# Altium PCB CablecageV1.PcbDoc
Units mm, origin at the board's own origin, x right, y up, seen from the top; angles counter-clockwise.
Board outline 55.12 x 24.93 mm, 2 copper layers (Top Layer, Bottom Layer); 4 components, 15 nets, 52 pads, 14 vias.
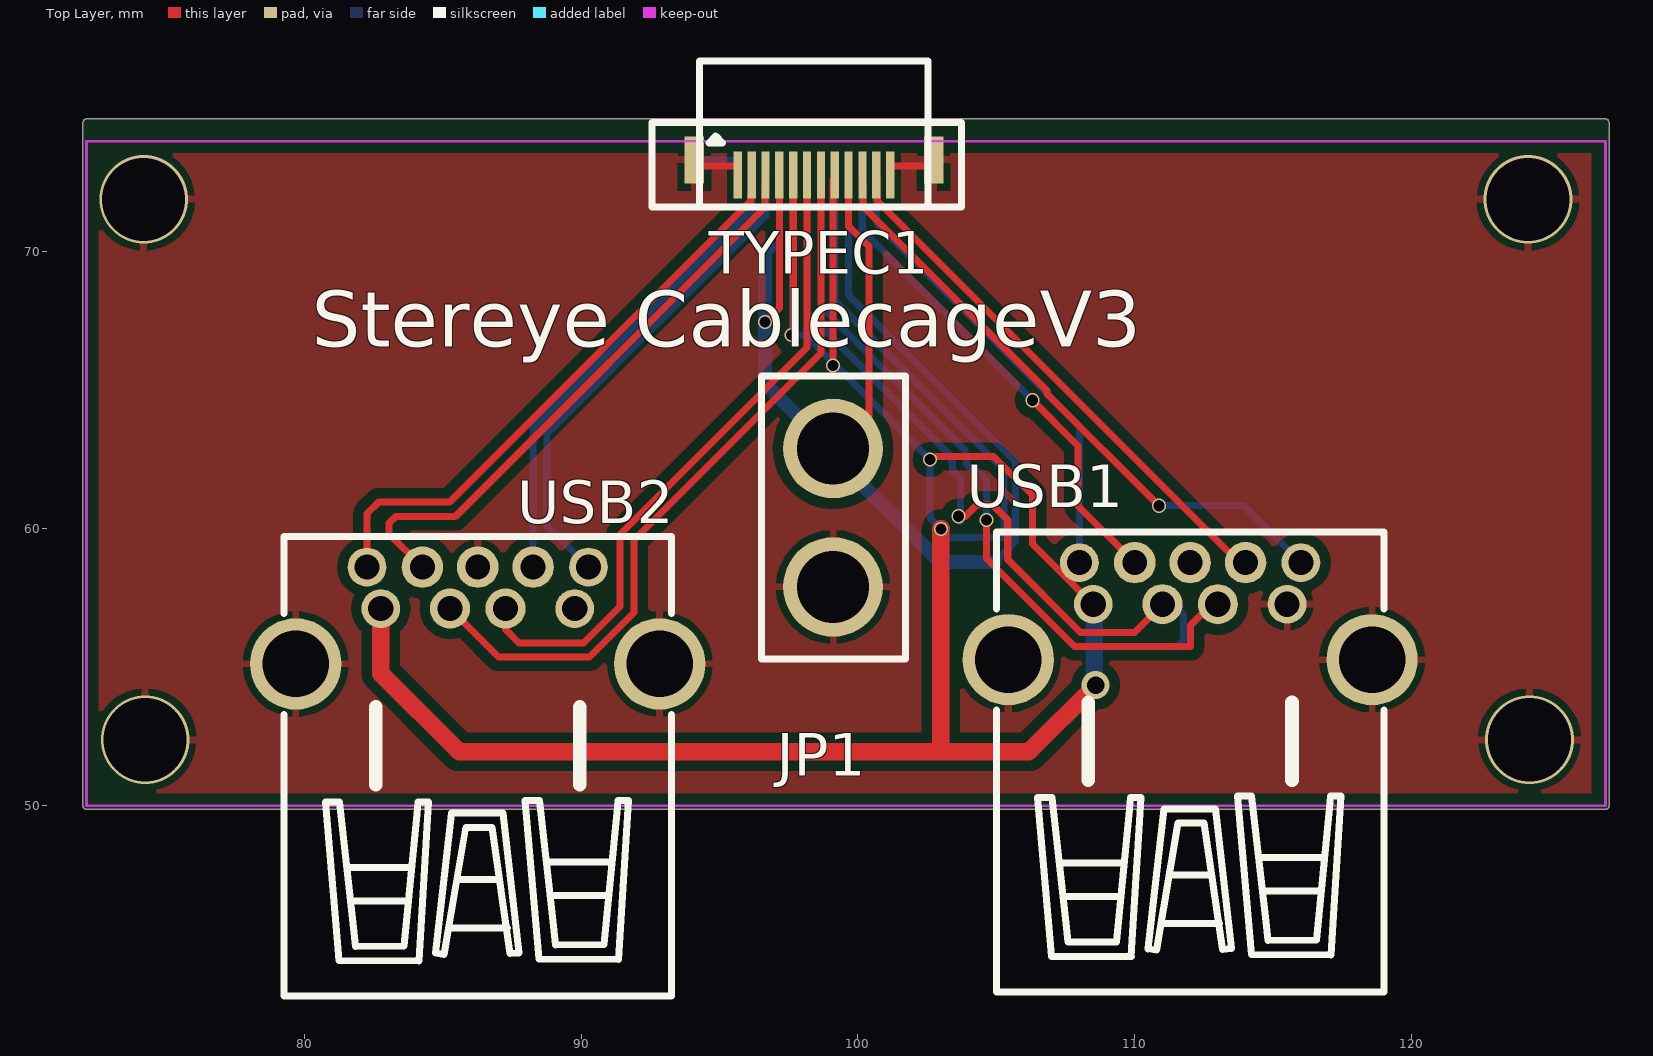
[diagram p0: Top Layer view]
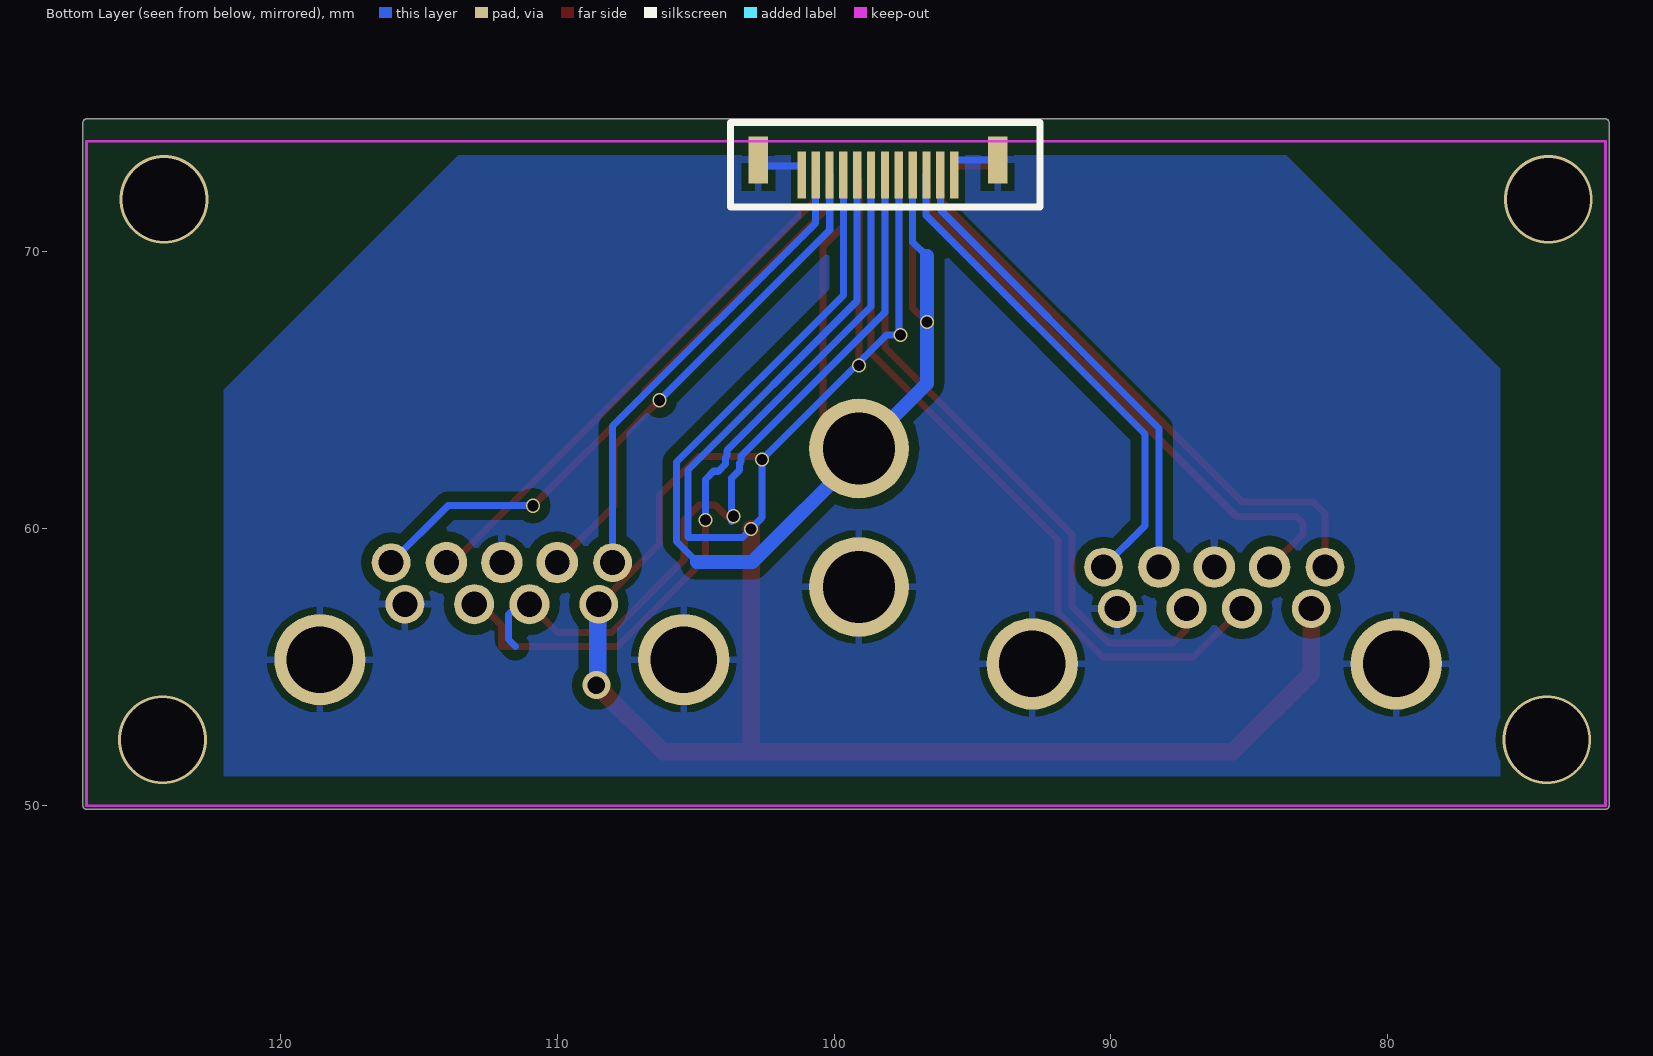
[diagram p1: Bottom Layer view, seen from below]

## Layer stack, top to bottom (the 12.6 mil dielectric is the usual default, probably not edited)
Top Solder: solder mask 0.0102, Solder Resist, Dk 3.5
Top Layer: signal copper 0.0356
Dielectric 1: dielectric 0.32, FR-4, Dk 4.8
Bottom Layer: signal copper 0.0356
Bottom Solder: solder mask 0.0102, Solder Resist, Dk 3.5

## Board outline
72.009,50 ccw(c72.136,50) 72.136,49.873 127,49.873 ccw(c127,50) 127.127,50 127.127,74.676 ccw(c127,74.676) 127,74.803 72.136,74.803 ccw(c72.136,74.676) 72.009,74.676

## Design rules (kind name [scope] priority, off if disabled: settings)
Clearance [All] p1: gap=0.152 ignorepadtopadclearanceinfootprint=TRUE except(0: Arc-Hole Track-Hole SMDPad-Hole THPad-Hole Via-Hole Fill-Hole Poly-Hole Region-Hole Text-Hole; 0.381: Arc-Fill Arc-Poly Arc-Region Track-Fill Track-Poly Track-Region SMDPad-Fill SMDPad-Poly SMDPad-Region THPad-Fill THPad-Poly THPad-Region Via-Fill Via-Poly Via-Region Fill-Fill Fill-Poly Fill-Region Poly-Poly Poly-Region Region-Region)
DiffPairsRouting [All] p1: maxlimit=0.381 minlimit=0.152 mostfreqgap=0.254 toplayer_minwidth=0.152 toplayer_maxwidth=0.381 toplayer_prefwidth=0.254 bottomlayer_minwidth=0.152 bottomlayer_maxwidth=0.381 bottomlayer_prefwidth=0.254 maxuncoupledlength=12.7
PlaneConnect [All] p1: planeconnectstyle=Relief reliefexpansion=0.508 reliefentries=4 reliefconductorwidth=0.381 reliefairgap=0.381
PolygonConnect [All] p1: connectstyle=Relief reliefconductorwidth=0.254 reliefentries=4 polygonreliefangle="90 Angle" airgapwidth=0.254
RoutingVias [All] p1: holewidth=0.711 width=1.27 viastyle="Through Hole" minholewidth=0.711 minwidth=1.27 maxholewidth=0.711 maxwidth=1.27
SolderMaskExpansion [All] p1: expansion=0.102
Width [All] p1: maxlimit=1.27 minlimit=0.152 preferedwidth=0.254 minimp=50.000000 maximp=50.000000 favimp=50.000000
28 further rules are at their usual default settings.

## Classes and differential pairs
differential pair USB3-T: +USB3-T_P -USB3-T_N
differential pair USB3-T2: +USB3-T2_P -USB3-T2_N
differential pair USB3-R: +USB3-R_P -USB3-R_N
differential pair USB3-R2: +USB3-R2_P -USB3-R2_N
differential pair D4: +D4_P -D4_N
differential pair D3: +D3_P -D3_N

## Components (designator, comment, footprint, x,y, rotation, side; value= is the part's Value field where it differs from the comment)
JP1 "HDR-1X2" XT30 99.1,60.4 r270 top
TYPEC1 "USB31-TYPEC-33141-2FS" TypeC-Chaban24P 98.41,71.628 r90 top
USB1 "FUS301-FDBU1K" USB3.0-A-TH_FUS301-FDBU1K 111.998,57.027 r0 top
USB2 "FUS301-FDBU1K" USB3.0-A-TH_FUS301-FDBU1K 86.267,56.868 r0 top

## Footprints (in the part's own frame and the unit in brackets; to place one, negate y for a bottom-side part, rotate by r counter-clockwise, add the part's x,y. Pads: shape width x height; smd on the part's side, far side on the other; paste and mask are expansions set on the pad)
TypeC-Chaban24P [mm]
  rect 1.7x0.7 smd: 0(1.693,4.317) 0(1.693,-4.323)
  rect 1.7x0.7 smd far side: 0(1.693,4.317) 0(1.693,-4.323)
  rect 1.7x0.3 smd: A1(1.143,2.747) A2(1.143,2.248) A3(1.143,1.748) A4(1.143,1.247) A5(1.143,0.747) A6(1.143,0.247) A7(1.143,-0.253) A8(1.143,-0.752) A9(1.143,-1.252) A10(1.143,-1.751) A11(1.143,-2.252) A12(1.143,-2.753)
  rect 1.7x0.3 smd far side: B1(1.143,-2.753) B2(1.143,-2.253) B3(1.143,-1.753) B4(1.143,-1.254) B5(1.143,-0.754) B6(1.143,-0.254) B7(1.143,0.247) B8(1.143,0.748) B9(1.143,1.248) B10(1.143,1.748) B11(1.143,2.247) B12(1.143,2.747)
  silkscreen extent -0.01,-5.33 5.27,5.84
USB3.0-A-TH_FUS301-FDBU1K [mm]
  round 1.4 hole 0.914: 1(-3.5,0.25) 4(3.5,0.25)
  round 1.45 hole 0.914: 2(-1,0.25) 3(1,0.25)
  round 1.4 hole 0.9: 5(4,1.75) 9(-4,1.75)
  round 1.5 hole 0.9: 6(2,1.75) 7(0,1.75) 8(-2,1.75)
  round 3.3 hole 2.4: 10(-6.57,-1.75) 10(6.57,-1.75)
  silkscreen extent -7,-13.75 7,2.85
XT30 [mm]
  round 3.6 hole 2.6: 1(-2.5,0) 2(2.5,0)
  silkscreen extent -5.12,-2.59 5.09,2.62

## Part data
JP1: library part "Header 2", "2P接插件"
TYPEC1: BOM_JLCPCB Part Class="Extended Part", BOM_Manufacturer="XKB Enterprise"
USB1 USB2: BOM_JLCPCB Part Class="Extended Part", BOM_Manufacturer=TXGA

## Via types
v1: diameter 0.508, hole 0.4, Top Layer to Bottom Layer, 9 vias
v2: diameter 3.2, hole 3, Top Layer to Bottom Layer, 4 vias
v3: diameter 1.016, hole 0.635, Top Layer to Bottom Layer, 1 vias

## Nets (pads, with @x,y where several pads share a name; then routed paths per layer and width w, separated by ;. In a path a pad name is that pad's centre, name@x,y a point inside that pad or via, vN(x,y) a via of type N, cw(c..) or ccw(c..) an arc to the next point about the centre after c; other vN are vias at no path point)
5V: TYPEC1.A5 TYPEC1.A8 TYPEC1.B5 TYPEC1.B8 USB1.1 USB2.1 | length 96.2
  Top Layer w0.254: v1@97.663,67 TYPEC1.A5 ; v1(99.1,65.9) 99.1,72.609 TYPEC1.A8@99.162,72.671 ; v1@102.8,62.6 102.811,62.611 104.902,62.611 106.299,61.214 106.299,59.455 108.477,57.277 USB1.1
  Top Layer w0.635: USB2.1 82.767,54.774 85.598,51.943 102.997,51.943 ; v1(103,60) 102.997,59.997 102.997,51.943 ; v3(108.585,54.356) 106.172,51.943 102.997,51.943
  Bottom Layer w0.254: TYPEC1.B8 97.661,67.061 v1(97.6,67) 98.1,67 v1(102.6,62.5) 102.6,60.4 v1(103,60) 103.313,59.687 105.258,59.687 105.283,59.712 105.283,60.444 105.279,60.448 105.279,62.121 99.163,68.237 TYPEC1.B5
  Bottom Layer w0.635: USB1.1 108.542,57.234 108.542,54.399 v3(108.585,54.356)
24V: JP1.1 TYPEC1.A4 TYPEC1.A9 TYPEC1.B4 TYPEC1.B9 | length 51.9
  Top Layer w0.254: v1(96.647,67.464) 97.162,67.98 TYPEC1.A4 ; TYPEC1.A9 99.661,70.939 100.4,70.2 100.4,63.57 JP1.1@100.203,63.373
  Bottom Layer w0.254: 96.647,69.843 97.162,70.358 TYPEC1.B9 ; TYPEC1.B4 99.663,68.437 105.686,62.414 105.686,60.616 105.689,60.613 105.689,59.543 104.946,58.8
  Bottom Layer w0.508: 96.647,69.843 v1(96.647,67.464) 96.647,65.253 JP1.1@98.9,63 ; JP1.1 99.1,62.653 102.953,58.8 104.946,58.8 ; JP1.1@99.419,62.45 JP1.1@100.243,63.274
D3_N: TYPEC1.A7 USB2.2 | length 26.6
  Top Layer w0.254: USB2.2 87.013,55.372 90.297,55.372 91.908,56.983 91.908,59.59 98.662,66.344 TYPEC1.A7
D3_P: TYPEC1.A6 USB2.3 | length 24
  Top Layer w0.254: USB2.3 87.267,56.37 87.757,55.88 90.087,55.88 91.4,57.193 91.4,59.8 98.154,66.554 TYPEC1.A6@98.154,72.771
D4_N: TYPEC1.B7 USB1.2 | length 27.7
  Top Layer w0.254: v1(103.632,60.452) 103.886,60.452 104.292,60.858 104.869,60.858 105.41,60.317 105.41,58.884 108.033,56.261 109.982,56.261 USB1.2
  Bottom Layer w0.254: TYPEC1.B7 98.162,67.819 103.353,62.629 103.353,62.422 103.406,62.368 103.406,62.126 103.695,61.837 v1@103.695,60.261 ; USB1.2 111.379,57.277 111.76,56.896 111.76,56.007 111.506,55.753
D4_P: TYPEC1.B6 USB1.3 | length 27.2
  Top Layer w0.254: v1(104.648,60.325) 104.648,58.928 107.823,55.753 112.014,55.753 112.014,56.515 112.776,57.277 USB1.3
  Bottom Layer w0.254: TYPEC1.B6@98.67,72.771 98.67,68.03 103.864,62.836 103.861,62.832 103.861,62.633 103.914,62.579 103.914,62.336 104.173,62.078 104.353,62.078 104.648,61.782 v1(104.648,60.325)
GND: JP1.2 TYPEC1.0 TYPEC1.A1 TYPEC1.A12 TYPEC1.B1 TYPEC1.B12 USB1.4 USB1.7 USB1.10 USB2.4 USB2.7 USB2.10 | length 8.3
  Top Layer w0.254: TYPEC1.0@94.093,73.321 94.316,73.098 95.639,73.098 95.662,73.075 TYPEC1.A1 ; TYPEC1.A12 101.162,73.075 101.185,73.098 102.509,73.098 TYPEC1.0@102.732,73.321
  Top Layer w0.635: USB1.7 USB1.7@111.998,59.011
  Bottom Layer w0.254: TYPEC1.0@94.093,73.321 95.639,73.321 95.662,73.298 TYPEC1.B12 ; TYPEC1.B1 101.162,73.075 101.185,73.098 102.509,73.098 TYPEC1.0@102.732,73.321
  other v2: 74.254,52.381 124.254,52.381 74.2,71.9 124.2,71.9
USB3-R2_N: TYPEC1.A10 USB1.5 | length 22
  Top Layer w0.254: TYPEC1.A10@100.177,72.412 100.177,71.643 106.832,64.988 106.832,64.872 v1(110.871,60.833)
  Bottom Layer w0.254: v1(110.871,60.833) 113.942,60.833 USB1.5
USB3-R2_P: TYPEC1.A11 USB1.6 | length 19.7
  Top Layer w0.254: TYPEC1.A11 100.685,72.748 100.685,71.854 113.761,58.777 USB1.6
USB3-R_N: TYPEC1.B10 USB2.5 | length 18
  Bottom Layer w0.254: USB2.5 88.775,60.11 88.775,63.419 96.67,71.314 TYPEC1.B10@96.67,72.771
USB3-R_P: TYPEC1.B11 USB2.6 | length 17.4
  Bottom Layer w0.254: USB2.6 88.267,63.629 96.162,71.524 TYPEC1.B11
USB3-T2_N: TYPEC1.B3 USB1.8 | length 18.1
  Top Layer w0.254: v1(106.299,64.643) 107.95,62.992 107.95,60.825 USB1.8
  Bottom Layer w0.254: TYPEC1.B3@100.155,72.771 100.155,70.787 v1(106.299,64.643)
USB3-T2_P: TYPEC1.B2 USB1.9 | length 17
  Bottom Layer w0.254: TYPEC1.B2 100.663,71.041 107.998,63.706 USB1.9
USB3-T_N: TYPEC1.A3 USB2.8 | length 21.1
  Top Layer w0.254: USB2.8 83.068,59.817 83.068,60.208 83.312,60.452 85.471,60.452 96.647,71.628 TYPEC1.A3@96.647,72.365
USB3-T_P: TYPEC1.A2 USB2.9 | length 20.7
  Top Layer w0.254: USB2.9 82.267,60.55 82.677,60.96 85.246,60.96 96.139,71.852 TYPEC1.A2@96.139,72.076

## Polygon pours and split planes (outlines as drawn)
GND on Top Layer "GND_L01_P004" (solid, remove dead copper, pour order 4): 72.517,74.295 72.517,50 126.492,50 126.492,74.295
GND on Bottom Layer "GND_L02_P006" (solid, remove dead copper, pour order 6): 83.66,73.5 75.946,65.786 75.946,51.054 122.047,51.054 122.047,65.024 113.571,73.5

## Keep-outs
Keep-Out Layer:
  lines w0.1: 72.136,50 72.136,74 127,74 127,50 72.136,50

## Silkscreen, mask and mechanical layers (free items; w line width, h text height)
Top Overlay:
  text "Stereye CablecageV3" at 80.264,66.567 h2.03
